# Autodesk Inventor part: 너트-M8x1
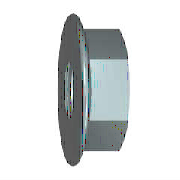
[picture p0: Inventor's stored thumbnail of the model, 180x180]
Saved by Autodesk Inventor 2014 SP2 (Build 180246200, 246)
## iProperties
Created: 2015-12
Part Number: 너트-M8x1
Material: 스테인리스강
Description: 플랜지붙이 6각 너트 - 일반 스레드
Document SubType Name: Modeling
Standard: ISO 4161
Designer: mdu
Standard Revision: 2판 1999-03-15
Standards Organization: ISO
Language: ko-KR
Size Designation: M8
Categories: <MemberInstance><Categories><Category DisplayName="조임쇠" InternalName="e4da775c-781d-43d5-af7c-5136215cf5a6" Mnemonic="FSTN"><Category DisplayName="너트" InternalN
Density: 8.08 g/cm^3
Appearance: 노란색
Mass: 9.03298 g
Surface Area: 8.90186 cm^2
Volume: 1.11794 cm^3
Author: mdu
IsCustomPart: 1
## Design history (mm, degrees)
sketch "스케치1"
  geometry: L1 (-1.844, 0)-(9.641, 0) reference; L2 (3.107, 6.5)-(2.288, 8.257); L3 (3.107, 6.5)-(8, 6.5); L4 (8, 6.5)-(8, 0); L5 (3.107, 6.5)-(3.107, 0); L6 (0, -1.835)-(0, 11.01) reference; A1 r 1.2 centre (1.2, 7.75) between (2.288, 8.257) and (0, 7.75); 1 further point
  constraints: 8 end point, 3 point on line, 2 perpendicular, 2 point on circle, 2 tangent, 1 centre point, 1 parallel
  dimensions: "d2" = 13 diameter of L3 L1 (= SW); "d4" = 17.9 dimension on A1 L1 (= LADI); "d5" = 1.2 radius of A1 (= PHH); "d15" = 8 distance between parallel lines of L4 L6 (= KOH); "d16" = 25 deg angle of L6 L2 (= KEWI)
revolve "링" sketch "스케치1" stored, may be unused: angle "d8" = 90 deg
sketch "스케치2"
  geometry: L1 (-6.5, -3.753)-(-6.5, 3.753); L2 (-6.5, 3.753)-(0, 7.506); L3 (0, 7.506)-(6.5, 3.753); L4 (6.5, 3.753)-(6.5, -3.753); L5 (6.5, -3.753)-(0, -7.506); L6 (0, -7.506)-(-6.5, -3.753); C1 r 4.9 at (0, 0); C2 r 7.75 at (0, 0) reference; 1 further point
  constraints: 12 end point, 1 centre point, 1 coincident, 1 vertical, 11 other
  dimensions: "d6" = 15.01111 distance of L5.end L2.end (= 1.1547 x SW)
extrude "본체" join sketch "스케치2" distance "d7" = 8 (= KOH); taper "d9" = 0 deg
sketch "스케치3"
  geometry: L1 (2.638, 7.506)-(8, 7.506) reference; L2 (8, 3.753)-(8, 7.506) reference; L3 (0, -7.75)-(0, 7.75) reference; L4 (-1.6, 0)-(9.6, 0) reference; L5 (7.419, 7.506)-(8, 6.5)
  constraints: 2 end point, 2 point on line
  dimensions: "d10" = 30 deg angle of L2 L5 (= ANG1); "d11" = 13 diameter of L5.end L4 (= SW0)
revolve "모따기1" sketch "스케치3" stored, may be unused: angle "d24" = 90 deg
sketch "스케치4"
  geometry: C1 r 7.75 at (0, 0) reference; 1 further point
  constraints: 1 coincident
hole "스레드" sketch "스케치4" at (0, 0) diameter "d25" = 6.647; stored, may be unused: countersink angle "d29" = 82 deg, drill point angle "d31" = 118 deg; dims "d26" = 6, "d27" = 4, "d28" = 2, "d30" = 8
workaxis "Work Axis1"
workplane "Work Plane1"
body "Solid1"
chamfer "모따기2" distance "d12" = 0.67658 (= -0.5 x GD1 + 0.5 x NND); stored, may be unused: angle "d13" = 30 deg, second distance "d46" = 0.67658 (= -0.5 x GD1 + 0.5 x NND)
chamfer "모따기3" distance "d51" = 0.67658 (= -0.5 x GD1 + 0.5 x NND); stored, may be unused: second distance "d52" = 2, angle "d53" = 45 deg
other parameters: "ANG1" = 30 deg [user parameter; used in 1 equation term], "KEWI" = 25 deg [user parameter; used in 1 equation term], "NND" = 8 [user parameter; used in 4 equation terms], "LADI" = 17.9 [user parameter; used in 2 equation terms], "SW" = 13 [user parameter; used in 3 equation terms], "PHH" = 1.2 [user parameter; used in 3 equation terms], "KOH" = 8 (= NND) [user parameter; used in 2 equation terms], "SW0" = 13 [user parameter; used in 1 equation term], "GD1" = 6.64684 (computed from THREADDIA, PTC, TOA) [user parameter; used in 3 equation terms], "d1" = 17.9 (= LADI), "d3" = 1.2 (= PHH), "d45" = 0, "d47" = 0, "d49" = 0, "d54" = 0, "GUL" = 0.67658 (= 0.541266 x PTC) [user parameter], "TPU" = 8 (computed from PTC) [user parameter], "RR" = 1.2 (= PHH) [user parameter], "THREADDIA" = 8 [user parameter; used in 1 equation term], "TOA" = 30 deg [user parameter; used in 1 equation term], "PTC" = 1.25 [user parameter; used in 4 equation terms], "GAL" = 0.67658 (= 0.541266 x PTC) [user parameter], "E0" = 15.015 (= 1.155 x SW) [user parameter]
